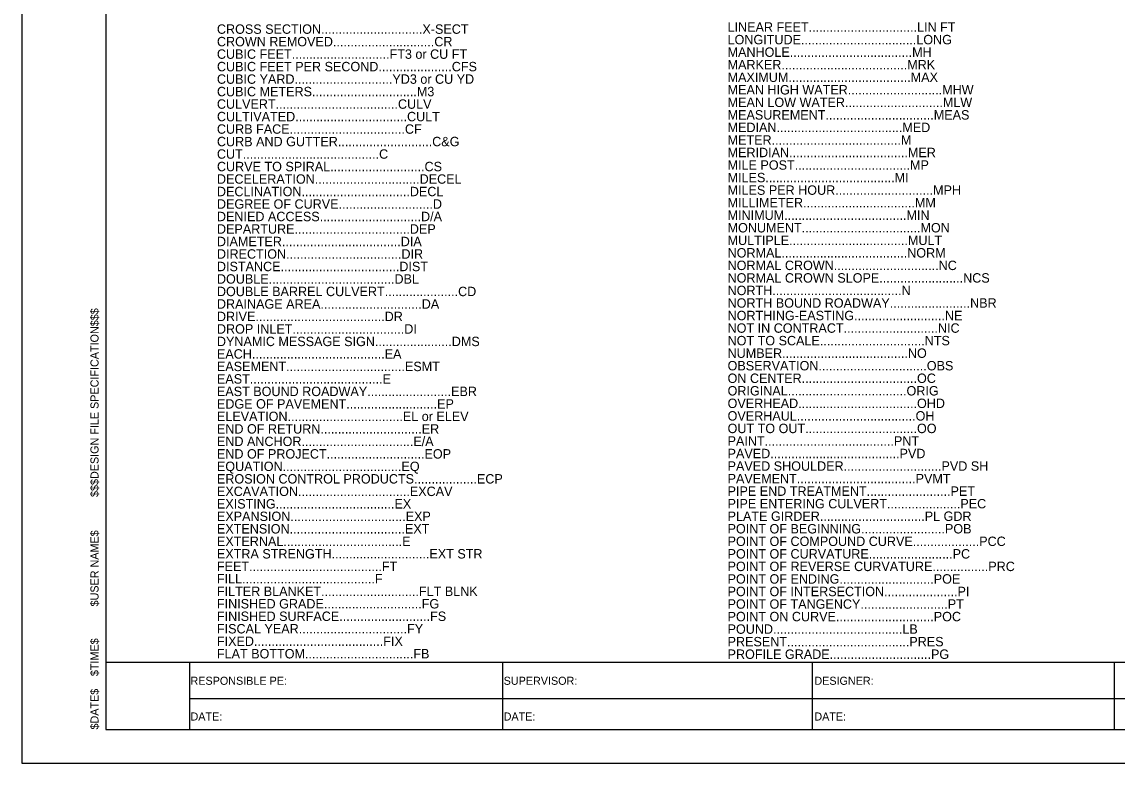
# Model space of a CAD drawing. Extents: x 0 to 1700, y 31 to 1131.
# Drawn here: x 0 to 815, y 31 to 582 of the extents above; entities that cross this region are included whole.
import ezdxf

# ---------------------------------------------------------------- set-up
doc = ezdxf.new("R2010")
doc.units = 0
for name, color, linetype in [('ANNO-TXT', 7, 'Continuous'), ('Level 1', 7, 'Continuous'), ('Level 62', 7, 'Continuous'), ('SHT-BDR', 7, 'Continuous'), ('SHT-BNDRY', 7, 'Continuous')]:
    doc.layers.add(name, color=color, linetype=linetype)

msp = doc.modelspace()

# ---------------------------------------------------------------- linework, layer by layer
at = {"layer": 'Level 62'}
msp.add_lwpolyline([(0, 30.66), (1700, 30.66), (1700, 1130.66), (0, 1130.66)], close=True, dxfattribs=at)
at = {"layer": 'SHT-BDR'}
msp.add_lwpolyline([(62.5, 105.71), (1675, 105.71)], dxfattribs=at)
at = {"layer": 'SHT-BNDRY'}
for p, q in [((124.99, 55.66), (124.99, 105.71)), ((357.6, 105.71), (357.6, 55.66)), ((588.31, 55.66), (588.31, 105.71)), ((812.93, 55.66), (812.93, 105.71)), ((124.99, 78.71), (903.12, 78.71))]:
    msp.add_line(p, q, dxfattribs=at)
msp.add_lwpolyline([(62.5, 55.66), (1675, 55.66), (1675, 1105.66), (62.5, 1105.66)], close=True, dxfattribs=at)

# ---------------------------------------------------------------- texts
at = {"layer": 'ANNO-TXT'}
for s, p in [('RESPONSIBLE PE:', (125.46, 88.93)), ('SUPERVISOR:', (358.48, 88.93)), ('DESIGNER:', (589.7, 88.93)), ('DATE:', (125.46, 62.34)), ('DATE:', (358.48, 62.34)), ('DATE:', (589.7, 62.34))]:
    msp.add_text(s, height=6, rotation=360, dxfattribs=at).set_placement(p)
at = {"layer": 'Level 1'}
for s, p in [('CROSS SECTION.............................X-SECT', (145.13, 573.35)), ('LINEAR FEET...............................LIN FT', (525.13, 574.88)), ('CROWN REMOVED.............................CR', (145.13, 564.05)), ('LONGITUDE.................................LONG', (525.13, 565.54)), ('MANHOLE...................................MH', (525.13, 556.21)), ('CUBIC FEET............................FT3 or CU FT', (145.13, 554.75)), ('CUBIC FEET PER SECOND.....................CFS', (145.13, 545.46)), ('MARKER....................................MRK', (525.13, 546.88)), ('CUBIC YARD............................YD3 or CU YD', (145.13, 536.16)), ('MAXIMUM...................................MAX', (525.13, 537.54)), ('CUBIC METERS..............................M3', (145.13, 526.87)), ('MEAN HIGH WATER...........................MHW', (525.13, 528.21)), ('CULVERT...................................CULV', (145.13, 517.57)), ('MEAN LOW WATER............................MLW', (525.13, 518.88)), ('CULTIVATED................................CULT', (145.13, 508.27)), ('MEASUREMENT...............................MEAS', (525.13, 509.54)), ('CURB FACE.................................CF', (145.13, 498.98)), ('MEDIAN....................................MED', (525.13, 500.21)), ('METER.....................................M', (525.13, 490.88)), ('CURB AND GUTTER...........................C&G', (145.13, 489.68)), ('CUT.......................................C', (145.13, 480.39)), ('MERIDIAN..................................MER', (525.13, 481.54)), ('CURVE TO SPIRAL...........................CS', (145.13, 471.09)), ('MILE POST.................................MP', (525.13, 472.21)), ('DECELERATION..............................DECEL', (145.13, 461.79)), ('MILES.....................................MI', (525.13, 462.88)), ('DECLINATION...............................DECL', (145.13, 452.5)), ('MILES PER HOUR............................MPH', (525.13, 453.54)), ('DEGREE OF CURVE...........................D', (145.13, 443.2)), ('MILLIMETER................................MM', (525.13, 444.21)), ('DENIED ACCESS.............................D/A', (145.13, 433.91)), ('MINIMUM...................................MIN', (525.13, 434.88)), ('MONUMENT..................................MON', (525.13, 425.54)), ('DEPARTURE.................................DEP', (145.13, 424.61)), ('DIAMETER..................................DIA', (145.13, 415.31)), ('MULTIPLE..................................MULT', (525.13, 416.21)), ('DIRECTION.................................DIR', (145.13, 406.02)), ('NORMAL....................................NORM', (525.13, 406.88)), ('DISTANCE..................................DIST', (145.13, 396.72)), ('NORMAL CROWN..............................NC', (525.13, 397.54)), ('DOUBLE....................................DBL', (145.13, 387.43)), ('NORMAL CROWN SLOPE........................NCS', (525.13, 388.21)), ('DOUBLE BARREL CULVERT.....................CD', (145.13, 378.13)), ('NORTH.....................................N', (525.13, 378.88)), ('DRAINAGE AREA.............................DA', (145.13, 368.83)), ('NORTH BOUND ROADWAY.......................NBR', (525.13, 369.54)), ('NORTHING-EASTING..........................NE', (525.13, 360.21)), ('DRIVE.....................................DR', (145.13, 359.54)), ('DROP INLET................................DI', (145.13, 350.24)), ('NOT IN CONTRACT...........................NIC', (525.13, 350.88)), ('DYNAMIC MESSAGE SIGN......................DMS', (145.13, 340.95)), ('NOT TO SCALE..............................NTS', (525.13, 341.54)), ('EACH......................................EA', (145.13, 331.65)), ('NUMBER....................................NO', (525.13, 332.21)), ('EASEMENT..................................ESMT', (145.13, 322.35)), ('OBSERVATION...............................OBS', (525.13, 322.88)), ('EAST......................................E', (145.13, 313.06)), ('ON CENTER.................................OC', (525.13, 313.54)), ('EAST BOUND ROADWAY........................EBR', (145.13, 303.76)), ('ORIGINAL..................................ORIG', (525.13, 304.21)), ('EDGE OF PAVEMENT..........................EP', (145.13, 294.47)), ('OVERHEAD..................................OHD', (525.13, 294.88)), ('ELEVATION.................................EL or ELEV', (145.13, 285.17)), ('OVERHAUL..................................OH', (525.13, 285.54)), ('END OF RETURN.............................ER', (145.13, 275.87)), ('OUT TO OUT................................OO', (525.13, 276.21)), ('END ANCHOR................................E/A', (145.13, 266.58)), ('PAINT.....................................PNT', (525.13, 266.88)), ('END OF PROJECT............................EOP', (145.13, 257.28)), ('PAVED.....................................PVD', (525.13, 257.54)), ('EQUATION..................................EQ', (145.13, 247.99)), ('PAVED SHOULDER............................PVD SH', (525.13, 248.21)), ('EROSION CONTROL PRODUCTS..................ECP', (145.13, 238.69)), ('PAVEMENT..................................PVMT', (525.13, 238.88)), ('EXCAVATION................................EXCAV', (145.13, 229.39)), ('PIPE END TREATMENT........................PET', (525.13, 229.54)), ('EXISTING..................................EX', (145.13, 220.1)), ('PIPE ENTERING CULVERT.....................PEC', (525.13, 220.21)), ('EXPANSION.................................EXP', (145.13, 210.8)), ('PLATE GIRDER..............................PL GDR', (525.13, 210.88)), ('EXTENSION.................................EXT', (145.13, 201.51)), ('POINT OF BEGINNING........................POB', (525.13, 201.54)), ('EXTERNAL..................................E', (145.13, 192.21)), ('POINT OF COMPOUND CURVE...................PCC', (525.13, 192.21)), ('EXTRA STRENGTH............................EXT STR', (145.13, 182.91)), ('POINT OF CURVATURE........................PC', (525.13, 182.88)), ('FEET......................................FT', (145.13, 173.62)), ('POINT OF REVERSE CURVATURE................PRC', (525.13, 173.54)), ('FILL......................................F', (145.13, 164.32)), ('POINT OF ENDING...........................POE', (525.13, 164.21)), ('FILTER BLANKET............................FLT BLNK', (145.13, 155.03)), ('POINT OF INTERSECTION.....................PI', (525.13, 154.88)), ('FINISHED GRADE............................FG', (145.13, 145.73)), ('POINT OF TANGENCY.........................PT', (525.13, 145.54)), ('FINISHED SURFACE..........................FS', (145.13, 136.43)), ('POINT ON CURVE............................POC', (525.13, 136.21)), ('FISCAL YEAR...............................FY', (145.13, 127.14)), ('POUND.....................................LB', (525.13, 126.88)), ('FIXED.....................................FIX', (145.13, 117.84)), ('PRESENT...................................PRES', (525.13, 117.54)), ('FLAT BOTTOM...............................FB', (145.13, 108.55)), ('PROFILE GRADE.............................PG', (525.13, 108.21))]:
    msp.add_text(s, height=7, dxfattribs=at).set_placement(p)
at = {"layer": 'SHT-BNDRY'}
for s, p in [('$$$DESIGN FILE SPECIFICATION$$$', (57.02, 228.66)), ('$USER NAME$', (57.02, 147.24)), ('$TIME$', (57.02, 95.39)), ('$DATE$', (57.02, 55.66))]:
    msp.add_text(s, height=6, rotation=90, dxfattribs=at).set_placement(p)

doc.saveas('drawing.dxf')
